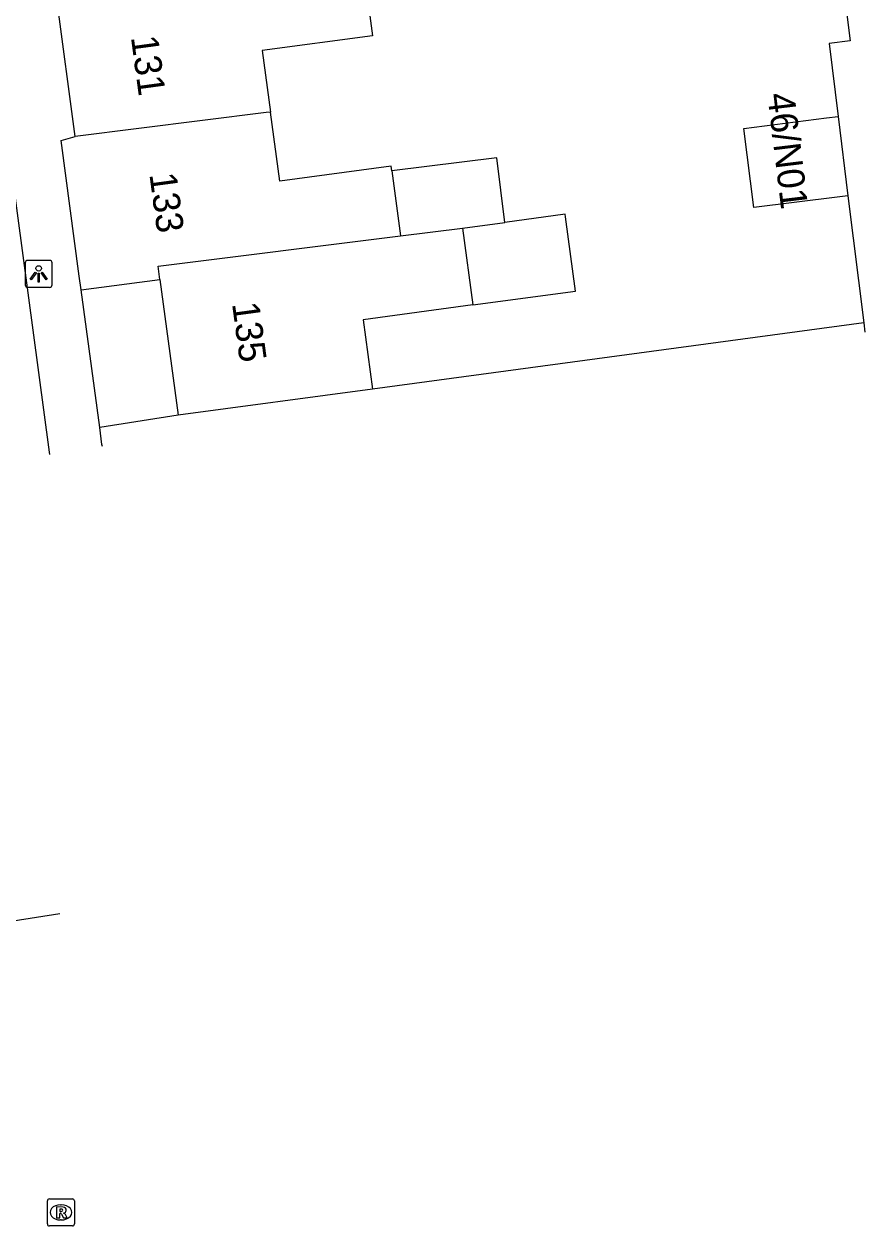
# Model space of a CAD drawing. Extents: x 163150 to 163546, y 380933 to 381635.
# Drawn here: x 163515.42 to 163546.45, y 381098.51 to 381142.86 of the extents above; entities that cross this region are included whole.
import ezdxf

# ---------------------------------------------------------------- set-up
doc = ezdxf.new("R2010")
doc.units = 0
for name, color, linetype in [('IMGEO_Lichtpunt', 7, 'Continuous'), ('IMGEO_Pand', 7, 'Continuous'), ('IMGEO_Pand_nummerreeks', 7, 'Continuous'), ('IMGEO_Rijbaan_lokaal_open', 7, 'Continuous'), ('IMGEO_Rioolput', 7, 'Continuous'), ('IMGEO_Voetpad_open', 7, 'Continuous')]:
    doc.layers.add(name, color=color, linetype=linetype)

msp = doc.modelspace()

# ---------------------------------------------------------------- linework, layer by layer
at = {"layer": 'IMGEO_Lichtpunt'}
for p, q in [((163515.462, 381134.048), (163515.462, 381133.241)), ((163515.462, 381134.048), (163515.462, 381133.241)), ((163516.364, 381134.143), (163515.556, 381134.143)), ((163516.364, 381134.143), (163515.556, 381134.143)), ((163516.458, 381133.241), (163516.458, 381134.048)), ((163516.458, 381133.241), (163516.458, 381134.048)), ((163515.556, 381133.147), (163516.364, 381133.147)), ((163515.556, 381133.147), (163516.364, 381133.147))]:
    msp.add_line(p, q, dxfattribs=at)
for points in [[(163515.836, 381133.712), (163515.875, 381133.684), (163515.687, 381133.422), (163515.649, 381133.449), (163515.836, 381133.712)], [(163515.938, 381133.664), (163515.985, 381133.664), (163515.985, 381133.342), (163515.938, 381133.342), (163515.938, 381133.664)], [(163516.048, 381133.684), (163516.086, 381133.711), (163516.273, 381133.449), (163516.234, 381133.421), (163516.048, 381133.684)]]:
    msp.add_lwpolyline(points, dxfattribs=at)
msp.add_circle((163515.961, 381133.846), 0.0994, dxfattribs=at)
for centre, start, end in [((163515.556, 381134.048), 90, 180), ((163515.556, 381134.048), 90, 180), ((163516.364, 381134.048), 0, 90), ((163516.364, 381134.048), 0, 90), ((163515.556, 381133.241), 180, 270), ((163515.556, 381133.241), 180, 270), ((163516.364, 381133.241), 270, 0), ((163516.364, 381133.241), 270, 360)]:
    msp.add_arc(centre, 0.0946, start, end, dxfattribs=at)
at = {"layer": 'IMGEO_Pand'}
for points in [[(163527.903, 381145.205), (163528.276, 381142.433), (163524.21, 381141.886), (163524.515, 381139.614)], [(163517.313, 381138.711), (163516.63, 381143.791)], [(163524.515, 381139.614), (163524.359, 381139.594), (163517.313, 381138.711)], [(163528.993, 381137.442), (163528.97, 381137.615), (163524.858, 381137.062), (163524.515, 381139.614)], [(163545.817, 381136.522), (163545.421, 381136.469), (163542.344, 381136.09), (163541.98, 381139.014), (163545.032, 381139.402), (163545.453, 381139.446)], [(163545.453, 381139.446), (163545.817, 381136.522)], [(163517.529, 381133.05), (163517.46, 381133.562), (163516.787, 381138.564), (163517.313, 381138.711)], [(163533.16, 381135.545), (163532.862, 381137.927), (163528.993, 381137.442)], [(163528.993, 381137.442), (163529.314, 381135.053)], [(163531.979, 381132.498), (163535.769, 381133.008), (163535.401, 381135.745), (163535.387, 381135.845), (163533.16, 381135.545)], [(163529.314, 381135.053), (163531.597, 381135.335)], [(163531.597, 381135.335), (163533.16, 381135.545)], [(163531.597, 381135.335), (163531.979, 381132.498)], [(163520.43, 381133.44), (163520.365, 381133.926), (163529.314, 381135.053)], [(163517.529, 381133.05), (163520.43, 381133.44)], [(163520.43, 381133.44), (163521.104, 381128.429)], [(163531.979, 381132.498), (163527.931, 381131.953), (163528.275, 381129.394)], [(163528.275, 381129.394), (163521.104, 381128.429)]]:
    msp.add_lwpolyline(points, dxfattribs=at)
at = {"layer": 'IMGEO_Rijbaan_lokaal_open'}
for points in [[(163545.254, 381147.457), (163545.895, 381142.238), (163545.122, 381142.143), (163545.453, 381139.446)], [(163545.817, 381136.522), (163546.401, 381131.833)], [(163546.401, 381131.833), (163546.445, 381131.489)], [(163516.743, 381110.026), (163515.019, 381109.754), (163513.54, 381109.521)]]:
    msp.add_lwpolyline(points, dxfattribs=at)
at = {"layer": 'IMGEO_Rioolput'}
for p, q in [((163516.281, 381098.584), (163516.281, 381099.436)), ((163516.356, 381099.51), (163517.208, 381099.51)), ((163516.769, 381099.29), (163516.794, 381099.29)), ((163517.282, 381099.436), (163517.282, 381098.584)), ((163517.208, 381098.51), (163516.356, 381098.51)), ((163516.792, 381098.73), (163516.767, 381098.73))]:
    msp.add_line(p, q, dxfattribs=at)
for points in [[(163516.281, 381098.584), (163516.281, 381099.436)], [(163516.356, 381099.51), (163517.208, 381099.51)], [(163517.282, 381099.436), (163517.282, 381098.584)], [(163516.87, 381099.208), (163516.618, 381099.21), (163516.618, 381098.81)], [(163516.618, 381098.81), (163516.742, 381098.81), (163516.742, 381098.972), (163516.753, 381098.972)], [(163516.796, 381099.129), (163516.742, 381099.129), (163516.742, 381099.048)], [(163516.742, 381099.048), (163516.794, 381099.048)], [(163516.8, 381098.943), (163516.871, 381098.81), (163517.011, 381098.81), (163516.946, 381098.936)], [(163517.208, 381098.51), (163516.356, 381098.51)]]:
    msp.add_lwpolyline(points, dxfattribs=at)
for centre, radius, start, end in [((163516.358, 381099.434), 0.0765, 91.552, 178.448), ((163516.358, 381099.434), 0.0765, 91.552, 178.448), ((163517.206, 381099.434), 0.0765, 1.552, 88.448), ((163517.206, 381099.434), 0.0765, 1.552, 88.448), ((163516.752, 381098.919), 0.0533, 26.0293, 88.6989), ((163516.778, 381099.237), 0.19, 274.7715, 282.9687), ((163516.802, 381099.033), 0.0964, 77.0061, 93.1865), ((163516.816, 381099.09), 0.0378, 276.6634, 79.6772), ((163516.869, 381099.098), 0.109, 350.3612, 89.416), ((163516.867, 381099.098), 0.112, 277.5842, 350.9817), ((163516.851, 381098.883), 0.108, 29.5134, 73.7905), ((163516.358, 381098.586), 0.0765, 181.552, 268.448), ((163516.358, 381098.586), 0.0765, 181.552, 268.448), ((163517.206, 381098.586), 0.0765, 271.552, 358.448), ((163517.206, 381098.586), 0.0765, 271.552, 358.448)]:
    msp.add_arc(centre, radius, start, end, dxfattribs=at)
for centre, major_axis, ratio, start_param, end_param in [((163516.768, 381099.01), (-0.387, 0.002), 0.722429, 4.712389, 7.853982), ((163516.793, 381099.01), (-0.39, 0.002), 0.717154, 1.570796, 4.712389)]:
    msp.add_ellipse(centre, major_axis=major_axis, ratio=ratio, start_param=start_param, end_param=end_param, dxfattribs=at)
at = {"layer": 'IMGEO_Voetpad_open'}
for points in [[(163505.712, 381206.244), (163508.536, 381185.012), (163509.233, 381180.183), (163516.345, 381127.061), (163516.355, 381126.983)], [(163518.211, 381127.971), (163517.529, 381133.05)], [(163546.401, 381131.833), (163528.275, 381129.394)], [(163521.104, 381128.429), (163518.211, 381127.971)], [(163518.312, 381127.276), (163518.295, 381127.348), (163518.211, 381127.971)]]:
    msp.add_lwpolyline(points, dxfattribs=at)

# ---------------------------------------------------------------- texts
at = {"layer": 'IMGEO_Pand_nummerreeks'}
for s, rotation, p in [('131', 277.6609, (163519.362, 381142.381)), ('46/N01', 276.8982, (163542.84, 381140.273)), ('133', 277.6602, (163520.043, 381137.32)), ('135', 277.6602, (163523.093, 381132.546))]:
    msp.add_text(s, height=1, rotation=rotation, dxfattribs=at).set_placement(p)

doc.saveas('drawing.dxf')
